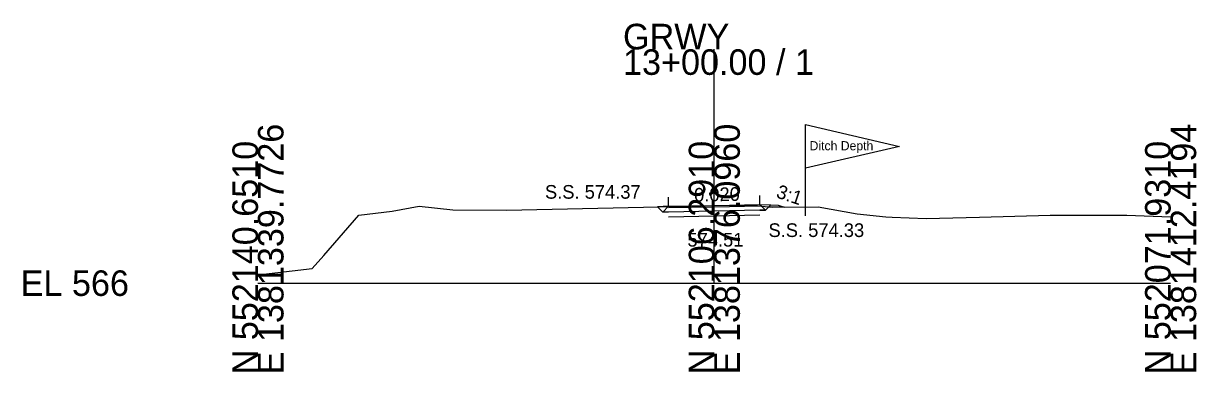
# Model space of a CAD drawing. Extents: x -26 to 103, y -10 to 3028.
# Drawn here: x -25.7 to 102.8, y 2990.3 to 3028.5 of the extents above; entities that cross this region are included whole.
import ezdxf

# ---------------------------------------------------------------- set-up
doc = ezdxf.new("R2010")
doc.units = 0
for name, color, linetype in [('Exist Cross Section Cell', 7, 'Continuous'), ('Exist XS Center Line Elevation Label', 7, 'Continuous'), ('Exist XS Ground Line', 7, 'Continuous'), ('Prop XS Ditch Slope Text', 7, 'Continuous'), ('Prop XS Dump Level', 7, 'Continuous'), ('Prop XS Earthwork Shape', 7, 'Continuous'), ('Prop XS EOT Tick Mark', 7, 'Continuous'), ('Prop XS Finish Grade', 7, 'Continuous'), ('Prop XS Finish Grade Earthwork', 7, 'Continuous'), ('Prop XS Finish Grade Pavement', 7, 'Continuous'), ('Prop XS Pvmt Edge Slope', 7, 'Continuous'), ('Prop XS SE Text', 7, 'Continuous'), ('Prop XS SS Elevation Text', 7, 'Continuous'), ('Prop XS Subgrade Earthwork', 7, 'Continuous')]:
    doc.layers.add(name, color=color, linetype=linetype)

msp = doc.modelspace()

# ---------------------------------------------------------------- linework, layer by layer
at = {"layer": 'Exist Cross Section Cell'}
for p, q in [((50, 3000), (50, 3025.64)), ((0, 3000), (50, 3000)), ((50, 3000), (100, 3000))]:
    msp.add_line(p, q, dxfattribs=at)
at = {"layer": 'Exist XS Ground Line'}
for p, q in [((11.06, 3007.47), (14.7, 3007.89)), ((14.7, 3007.89), (17.67, 3008.46)), ((17.67, 3008.46), (21.35, 3008.03)), ((21.35, 3008.03), (27.23, 3008.01)), ((27.23, 3008.01), (42.26, 3008.34)), ((42.26, 3008.34), (45.71, 3008.4)), ((45.71, 3008.4), (50, 3008.51)), ((50, 3008.51), (51.68, 3008.55)), ((51.68, 3008.55), (54.32, 3008.53)), ((54.32, 3008.53), (56.36, 3008.32)), ((56.36, 3008.32), (61.39, 3008.36)), ((61.39, 3008.36), (65.64, 3007.61)), ((7.22, 3003.04), (11.06, 3007.47)), ((65.64, 3007.61), (68.81, 3007.28)), ((68.81, 3007.28), (69.49, 3007.22)), ((69.49, 3007.22), (73.2, 3007.1)), ((73.2, 3007.1), (79.06, 3007.24)), ((79.06, 3007.24), (86.81, 3007.47)), ((86.81, 3007.47), (95.2, 3007.46)), ((95.2, 3007.46), (100, 3007.27)), ((5.94, 3001.6), (7.22, 3003.04)), ((0, 3000.92), (5.94, 3001.6))]:
    msp.add_line(p, q, dxfattribs=at)
at = {"layer": 'Prop XS Dump Level'}
for p, q in [((60, 3012.6), (60, 3017.4)), ((60, 3017.4), (70.3, 3015)), ((70.3, 3015), (60, 3012.6)), ((60, 3007.4), (60, 3012.6)), ((45, 3008.28), (50, 3008.38)), ((50, 3008.38), (55, 3008.48)), ((45, 3007.28), (50, 3007.38)), ((50, 3007.38), (55, 3007.48))]:
    msp.add_line(p, q, dxfattribs=at)
at = {"layer": 'Prop XS Earthwork Shape'}
for points in [[(55, 3008.01), (50, 3007.9), (45, 3007.8), (44.36, 3007.79), (43.79, 3008.37), (45.71, 3008.4), (50, 3008.51), (51.68, 3008.55), (54.32, 3008.53), (55.96, 3008.36), (55.61, 3008.02)], [(55.96, 3008.36), (56.18, 3008.58), (57, 3008.55), (57.67, 3008.33), (56.36, 3008.32)]]:
    msp.add_lwpolyline(points, close=True, dxfattribs=at)
at = {"layer": 'Prop XS EOT Tick Mark'}
for p, q in [((45, 3008.43), (45, 3009.43)), ((55, 3008.63), (55, 3009.63))]:
    msp.add_line(p, q, dxfattribs=at)
at = {"layer": 'Prop XS Finish Grade'}
for p, q in [((45, 3008.43), (43.79, 3008.37)), ((55, 3008.63), (56.18, 3008.58))]:
    msp.add_line(p, q, dxfattribs=at)
at = {"layer": 'Prop XS Finish Grade Earthwork'}
for p, q in [((56.18, 3008.58), (57, 3008.55)), ((57, 3008.55), (57.67, 3008.33))]:
    msp.add_line(p, q, dxfattribs=at)
at = {"layer": 'Prop XS Finish Grade Pavement'}
for p, q in [((45, 3008.43), (50, 3008.53)), ((50, 3008.53), (55, 3008.63))]:
    msp.add_line(p, q, dxfattribs=at)
at = {"layer": 'Prop XS Pvmt Edge Slope'}
for p, q in [((45, 3008.43), (44.36, 3007.79)), ((55, 3008.63), (55.61, 3008.02))]:
    msp.add_line(p, q, dxfattribs=at)
at = {"layer": 'Prop XS Subgrade Earthwork'}
for p, q in [((44.36, 3007.79), (43.79, 3008.37)), ((45, 3007.8), (44.36, 3007.79)), ((50, 3007.9), (45, 3007.8)), ((55, 3008.01), (50, 3007.9)), ((55, 3008.01), (55.61, 3008.02)), ((55.61, 3008.02), (56.18, 3008.58))]:
    msp.add_line(p, q, dxfattribs=at)

# ---------------------------------------------------------------- texts
at = {"layer": 'Exist Cross Section Cell'}
for s, p in [('GRWY', (40, 3025.64)), ('13+00.00 / 1', (40, 3022.84)), ('EL 566', (-26, 2998.6))]:
    msp.add_text(s, height=2.8, dxfattribs=at).set_placement(p)
for s, p in [('E 1381339.7726', (2.8, 2990)), ('E 1381376.0960', (52.8, 2990)), ('E 1381412.4194', (102.8, 2990)), ('N 552140.6510', (0, 2990)), ('N 552106.2910', (50, 2990)), ('N 552071.9310', (100, 2990))]:
    msp.add_text(s, height=2.8, rotation=90, dxfattribs=at).set_placement(p)
at = {"layer": 'Exist XS Center Line Elevation Label'}
msp.add_text('574.51', height=1.5, dxfattribs=at).set_placement((47.06, 3004.01))
at = {"layer": 'Prop XS Ditch Slope Text'}
msp.add_text('3:1', height=1.5, rotation=341.5651, dxfattribs=at).set_placement((56.69, 3009.42))
at = {"layer": 'Prop XS Dump Level'}
for s, height, p in [('Ditch Depth', 1, (60.44, 3014.57)), ('Case1', 0.04, (43, 3008.08)), ('Case1', 0.04, (57, 3008.36))]:
    msp.add_text(s, height=height, dxfattribs=at).set_placement(p)
at = {"layer": 'Prop XS SE Text'}
msp.add_text('0.020', height=1.5, rotation=1.1458, dxfattribs=at).set_placement((47.8, 3008.93))
at = {"layer": 'Prop XS SS Elevation Text'}
for s, p in [('S.S. 574.37', (31.45, 3009.26)), ('S.S. 574.33', (55.94, 3005.06))]:
    msp.add_text(s, height=1.5, dxfattribs=at).set_placement(p)

doc.saveas('drawing.dxf')
